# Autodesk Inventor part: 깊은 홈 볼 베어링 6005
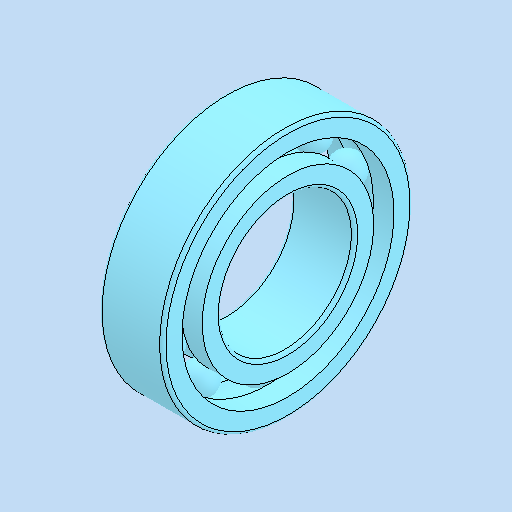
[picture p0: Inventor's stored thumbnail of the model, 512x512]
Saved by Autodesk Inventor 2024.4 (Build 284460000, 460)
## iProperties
Created: 2025-11
Part Number: 깊은 홈 볼 베어링 6005
Material: 강철, 연강
Description: 깊은 그루브 볼 베어링
Document SubType Name: Modeling
Designer: home
Density: 7.85 g/cm^3
Appearance: 기본값
Author: jhkim
Sending System: Autodesk Inventor 2026
Preprocessor: ST-DEVELOPER v20.1
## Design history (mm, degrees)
feature "Solid1"
feature "Solid1:1"
feature "Solid1:2"
feature "Solid1:3"
feature "Solid1:4"
feature "Solid1:5"
feature "Solid1:6"
feature "Solid1:7"
feature "Solid1:8"
feature "Solid1:9"
feature "Solid1:10"
feature "Solid1:11"
node "솔리드1"
node "솔리드2"
node "솔리드3"
node "솔리드4"
node "솔리드5"
node "솔리드6"
node "솔리드7"
node "솔리드8"
node "솔리드9"
node "솔리드10"
node "솔리드11"
node "솔리드12"
